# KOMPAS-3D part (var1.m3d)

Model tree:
1. ВЗ
2. Эскиз:1
3. Операция выдавливания:7
     Расстояние 1 = 150
4. Палуба
5. Эскиз:12
6. Операция вращения:2
     Угол 1 = 360
7. Турбина
8. jcm
     Расстояние = 75
9. ВЗ 1
     Расстояние = 50
10. ВЗ 2
     Расстояние = 50
11. ВЗ 3
     Расстояние = 50
12. ВЗ 4
     Расстояние = 50
13. ВЗ 5
     Расстояние = 50
14. ВЗ 6
     Расстояние = 50
15. Эскиз:9
16. Операция выдавливания:4
     Расстояние 1 = 65; Расстояние 2 = 60
17. Эскиз:10
18. Операция выдавливания:5
     Расстояние 1 = 65; Расстояние 2 = 70
19. Булева операция:2
20. Эскиз:11
21. Операция выдавливания:6
     Расстояние 1 = 545; Расстояние 2 = 360
22. Булева операция:3
23. Зеркальное отражение:3
24. ВЗ 7
     Расстояние = 50
25. ВЗ  8
     Расстояние = 48
26. Эскиз:13
27. Эскиз:14
28. Эскиз:15
29. Макро:18
30. аваы
31. боковые понтоны
32. Эскиз:16
33. Операция вращения:3
     Угол 1 = 360
34. вырез под турбину
35. Булева операция:5
36. Палуба с вырезом
37. сечение воздухозаборника
38. кривая
39. траектория воздухозаборника
40. траектория губы
41. вырез
     Толщина стенки 1 = 2; Толщина стенки 2 = 2
42. Кинематическая операция:2
     Толщина стенки 1 = 2; Толщина стенки 2 = 2
43. Кинематическая операция:3
     Толщина стенки 1 = 2; Толщина стенки 2 = 2
44. Булева операция:6
45. кабина1
46. Булева операция:7
47. труба
     Толщина стенки 1 = 2; Толщина стенки 2 = 2
48. Воздухозаборник
49. Эскиз:21
50. Правый киль
     Толщина стенки 1 = 1; Толщина стенки 2 = 1; Расстояние 1 = 7; Расстояние 2 = 360
51. Левый киль
52. Киль1
53. Эскиз:22
54. Операция выдавливания:9
     Расстояние 1 = 125; Расстояние 2 = 125
55. стабилизатор1
56. Эскиз:23
57. эск
     Толщина стенки 1 = 2; Толщина стенки 2 = 2
58. Губа
59. Корпус1
60. Смещенная плоскость:1
     Расстояние = 40
61. плоскости
62. Сечение поверхностью:1
63. Сечение поверхностью:2
64. Сечение поверхностью:3
65. Сечение поверхностью:4
66. Сечение поверхностью:5
67. Сечение поверхностью:6
68. Сечение поверхностью:7
69. Сечения для вывода
